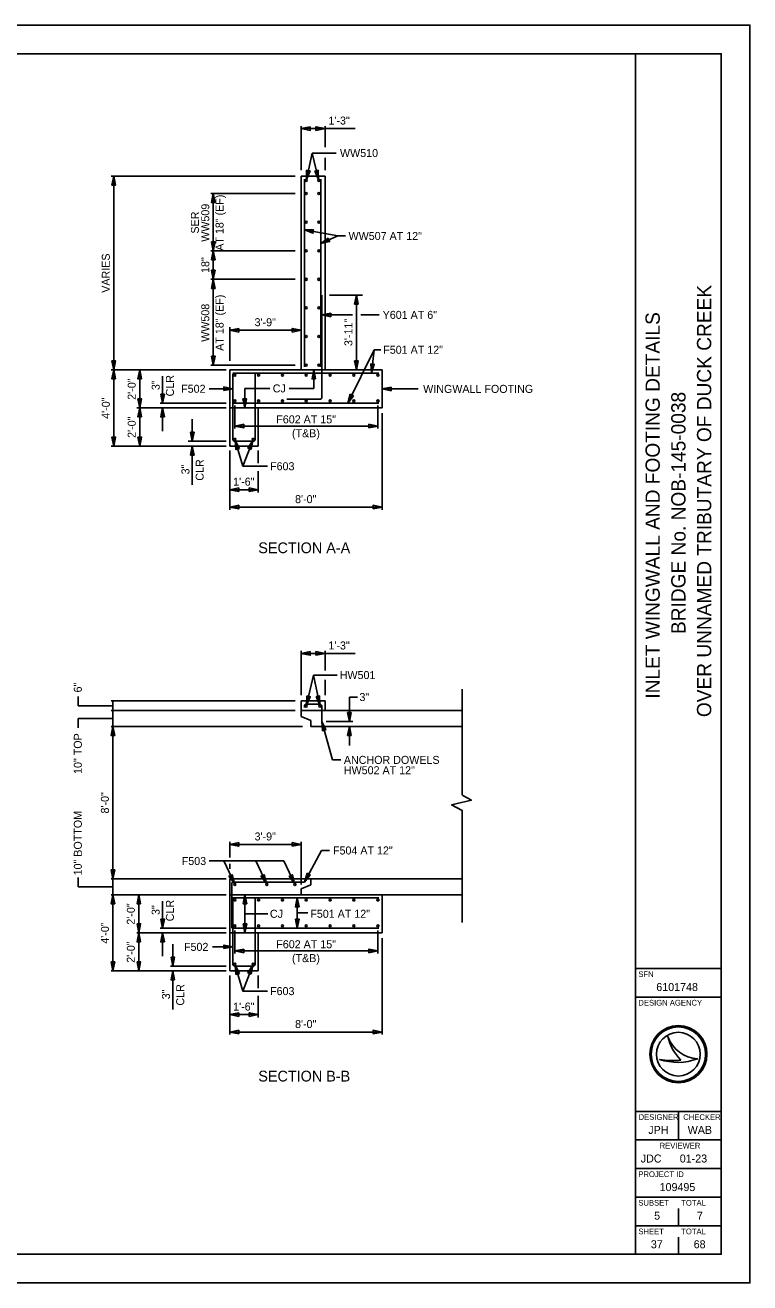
# Model space of a CAD drawing. Extents: x -375 to 456, y -77 to 177.
# Drawn here: x 64 to 102, y 0 to 66 of the extents above; entities that cross this region are included whole.
import ezdxf

# ---------------------------------------------------------------- set-up
doc = ezdxf.new("R2010")
doc.units = 0
for name, color, linetype in [('BR_P_Gen_Text', 7, 'Continuous'), ('BR_P_Slab_Reinforcing', 7, 'Continuous'), ('BR_P_Sub_Deep_Reinforcing', 7, 'Continuous'), ('DR_P_Culvert', 7, 'Continuous'), ('SH_Border', 7, 'Continuous'), ('SH_Cut_Line', 7, 'Continuous'), ('SH_Data', 7, 'Continuous'), ('TX_P_1', 7, 'Continuous')]:
    doc.layers.add(name, color=color, linetype=linetype)

msp = doc.modelspace()

# ---------------------------------------------------------------- linework, layer by layer
at = {"layer": 'BR_P_Gen_Text'}
for points in [[(78.928, 60.667), (78.928, 60.478), (78.456, 60.573)], [(79.233, 60.478), (79.233, 60.667), (79.706, 60.573)], [(78.737, 58.391), (78.922, 58.351), (78.73, 57.909)], [(79.165, 58.344), (79.349, 58.39), (79.372, 57.908)], [(68.717, 57.606), (68.528, 57.606), (68.623, 58.078)], [(73.939, 56.689), (73.75, 56.689), (73.844, 57.162)], [(79.104, 55.262), (79.071, 55.076), (78.622, 55.252)], [(79.875, 54.819), (79.95, 54.646), (79.479, 54.545)], [(73.75, 54.634), (73.939, 54.634), (73.844, 54.162)], [(73.939, 53.689), (73.75, 53.689), (73.844, 54.162)], [(73.75, 53.134), (73.939, 53.134), (73.844, 52.662)], [(73.939, 52.189), (73.75, 52.189), (73.844, 52.662)], [(81.448, 51.359), (81.259, 51.359), (81.353, 51.832)], [(80.011, 50.89), (80.011, 50.701), (79.539, 50.796)], [(75.178, 50.086), (75.178, 49.897), (74.706, 49.992)], [(77.983, 49.897), (77.983, 50.086), (78.456, 49.992)], [(68.528, 48.384), (68.717, 48.384), (68.623, 47.912)], [(73.75, 48.634), (73.939, 48.634), (73.844, 48.162)], [(81.259, 48.384), (81.448, 48.384), (81.353, 47.912)], [(82.106, 48.226), (82.293, 48.203), (82.142, 47.745)], [(68.717, 47.439), (68.528, 47.439), (68.623, 47.912)], [(70.078, 47.439), (69.889, 47.439), (69.983, 47.912)], [(79.213, 47.439), (79.024, 47.439), (79.118, 47.912)], [(74.4, 46.825), (74.4, 47.014), (74.872, 46.919)], [(83.178, 47.006), (83.178, 46.817), (82.706, 46.912)], [(69.889, 46.384), (70.078, 46.384), (69.983, 45.912)], [(71.087, 46.634), (71.276, 46.634), (71.182, 46.162)], [(75.401, 46.384), (75.59, 46.384), (75.495, 45.912)], [(81.028, 46.627), (81.198, 46.543), (80.903, 46.162)], [(70.078, 45.439), (69.889, 45.439), (69.983, 45.912)], [(71.276, 45.439), (71.087, 45.439), (71.182, 45.912)], [(75.445, 45.056), (75.445, 44.867), (74.972, 44.962)], [(82.013, 44.867), (82.013, 45.056), (82.485, 44.962)], [(68.528, 44.384), (68.717, 44.384), (68.623, 43.912)], [(69.889, 44.384), (70.078, 44.384), (69.983, 43.912)], [(72.648, 44.634), (72.837, 44.634), (72.742, 44.162)], [(72.837, 43.439), (72.648, 43.439), (72.742, 43.912)], [(75.215, 43.785), (75.034, 43.73), (74.988, 44.21)], [(75.838, 43.736), (75.662, 43.804), (75.919, 44.211)], [(75.178, 41.717), (75.178, 41.528), (74.706, 41.622)], [(75.733, 41.528), (75.733, 41.717), (76.206, 41.622)], [(75.178, 40.802), (75.178, 40.613), (74.706, 40.707)], [(82.233, 40.613), (82.233, 40.802), (82.706, 40.707)], [(78.928, 33.123), (78.928, 32.934), (78.456, 33.028)], [(79.233, 32.934), (79.233, 33.123), (79.706, 33.028)], [(78.749, 30.802), (78.933, 30.759), (78.735, 30.32)], [(79.24, 30.763), (79.425, 30.802), (79.429, 30.32)], [(80.889, 29.923), (81.078, 29.923), (80.983, 29.451)], [(68.67, 28.728), (68.481, 28.728), (68.576, 29.201)], [(79.758, 29.022), (79.576, 28.97), (79.539, 29.451)], [(81.078, 28.728), (80.889, 28.728), (80.983, 29.201)], [(75.178, 23.1), (75.178, 22.911), (74.706, 23.006)], [(77.983, 22.911), (77.983, 23.1), (78.456, 23.006)], [(68.481, 21.673), (68.67, 21.673), (68.576, 21.201)], [(74.664, 21.338), (74.836, 21.418), (74.949, 20.95)], [(76.344, 21.338), (76.515, 21.418), (76.629, 20.95)], [(77.821, 21.338), (77.993, 21.418), (78.106, 20.95)], [(78.769, 21.495), (78.935, 21.405), (78.628, 21.034)], [(68.67, 19.895), (68.481, 19.895), (68.576, 20.367)], [(70.031, 19.895), (69.842, 19.895), (69.936, 20.367)], [(75.598, 19.895), (75.409, 19.895), (75.504, 20.367)], [(78.343, 19.728), (78.154, 19.728), (78.249, 20.201)], [(69.842, 18.84), (70.031, 18.84), (69.936, 18.367)], [(71.087, 19.09), (71.276, 19.09), (71.182, 18.617)], [(75.409, 18.84), (75.598, 18.84), (75.504, 18.367)], [(78.154, 19.09), (78.343, 19.09), (78.249, 18.617)], [(70.031, 17.895), (69.842, 17.895), (69.936, 18.367)], [(71.276, 17.895), (71.087, 17.895), (71.182, 18.367)], [(74.4, 17.537), (74.4, 17.726), (74.872, 17.631)], [(75.445, 17.512), (75.445, 17.323), (74.972, 17.417)], [(82.013, 17.323), (82.013, 17.512), (82.485, 17.417)], [(68.481, 16.84), (68.67, 16.84), (68.576, 16.367)], [(69.842, 16.84), (70.031, 16.84), (69.936, 16.367)], [(71.627, 17.09), (71.816, 17.09), (71.722, 16.617)], [(75.215, 16.24), (75.034, 16.186), (74.988, 16.665)], [(75.838, 16.192), (75.662, 16.26), (75.919, 16.667)], [(71.816, 15.895), (71.627, 15.895), (71.722, 16.367)], [(75.178, 14.172), (75.178, 13.983), (74.706, 14.078)], [(75.733, 13.983), (75.733, 14.172), (76.206, 14.078)], [(75.178, 13.257), (75.178, 13.068), (74.706, 13.163)], [(82.233, 13.068), (82.233, 13.257), (82.706, 13.163)]]:
    msp.add_lwpolyline(points, close=True, dxfattribs=at)
at = {"layer": 'BR_P_Slab_Reinforcing'}
for centre in [(78.719, 57.856), (79.385, 57.856), (78.719, 57.162), (79.385, 57.162), (78.719, 55.662), (79.385, 55.662), (78.719, 54.162), (79.385, 54.162), (78.719, 52.662), (79.385, 52.662), (78.719, 51.162), (79.385, 51.162), (78.719, 49.662), (79.385, 49.662), (78.719, 48.162), (79.385, 48.162), (74.972, 47.637), (76.222, 47.637), (77.472, 47.637), (78.722, 47.637), (79.972, 47.637), (81.222, 47.637), (82.485, 47.637), (74.972, 46.276), (76.222, 46.276), (77.472, 46.276), (78.722, 46.276), (79.972, 46.276), (81.222, 46.276), (82.485, 46.276), (74.972, 44.262), (75.939, 44.262), (78.722, 30.267), (79.441, 30.267), (74.972, 20.901), (76.652, 20.901), (78.129, 20.901), (74.972, 20.093), (76.222, 20.093), (77.472, 20.093), (78.722, 20.093), (79.972, 20.093), (81.222, 20.093), (82.485, 20.093), (74.972, 18.731), (76.222, 18.731), (77.472, 18.731), (78.722, 18.731), (79.972, 18.731), (81.222, 18.731), (82.485, 18.731), (74.972, 16.717), (75.939, 16.717)]:
    msp.add_circle(centre, 0.0542, dxfattribs=at)
at = {"layer": 'BR_P_Sub_Deep_Reinforcing'}
for p, q in [((78.622, 48.078), (78.622, 57.912)), ((79.479, 48.078), (79.479, 57.912)), ((79.539, 46.465), (79.539, 51.832)), ((82.539, 47.745), (74.872, 47.745)), ((74.872, 47.707), (74.872, 44.262)), ((76.039, 44.262), (76.039, 47.707)), ((77.709, 46.365), (79.439, 46.365)), ((82.539, 46.162), (74.872, 46.162)), ((74.972, 44.162), (75.939, 44.162)), ((79.439, 30.367), (78.722, 30.367)), ((78.622, 30.267), (78.622, 30.201)), ((79.539, 29.451), (79.539, 30.267)), ((74.812, 18.617), (74.812, 20.934)), ((74.912, 21.034), (78.628, 21.034)), ((82.539, 20.201), (74.872, 20.201)), ((74.872, 20.163), (74.872, 16.717)), ((76.039, 16.717), (76.039, 20.163)), ((82.539, 18.617), (74.872, 18.617)), ((74.972, 16.617), (75.939, 16.617))]:
    msp.add_line(p, q, dxfattribs=at)
for centre, start, end in [((79.439, 46.465), 270, 0), ((74.972, 44.262), 180, 270), ((75.939, 44.262), 270, 0), ((78.722, 30.267), 90, 180), ((79.439, 30.267), 0, 90), ((74.912, 20.934), 90, 180), ((74.972, 16.717), 180, 270), ((75.939, 16.717), 270, 360)]:
    msp.add_arc(centre, 0.1, start, end, dxfattribs=at)
at = {"layer": 'DR_P_Culvert'}
for p, q in [((78.456, 47.912), (78.456, 58.078)), ((78.456, 58.078), (79.706, 58.078)), ((79.706, 47.912), (79.706, 58.078)), ((78.456, 47.912), (74.706, 47.912)), ((74.706, 47.912), (74.706, 43.912)), ((78.456, 47.912), (79.706, 47.912)), ((82.706, 47.912), (79.706, 47.912)), ((82.706, 47.912), (82.706, 45.912)), ((76.206, 45.912), (74.706, 45.912)), ((82.706, 45.912), (76.206, 45.912)), ((76.206, 45.912), (76.206, 43.912)), ((76.206, 43.912), (74.706, 43.912)), ((86.896, 31.149), (86.896, 25.656)), ((78.456, 30.034), (78.456, 30.534)), ((78.456, 30.534), (79.706, 30.534)), ((79.706, 30.034), (79.706, 30.534)), ((78.456, 30.034), (86.896, 30.034)), ((78.456, 30.034), (78.456, 29.721)), ((78.456, 29.721), (78.956, 29.513)), ((78.956, 29.513), (78.956, 29.201)), ((78.956, 29.201), (86.896, 29.201)), ((78.956, 21.201), (74.706, 21.201)), ((74.706, 20.367), (74.706, 21.201)), ((78.956, 21.201), (86.896, 21.201)), ((78.956, 20.888), (78.956, 21.201)), ((78.456, 20.68), (78.956, 20.888)), ((78.456, 20.367), (78.456, 20.68)), ((74.706, 20.367), (74.706, 16.367)), ((78.456, 20.367), (74.706, 20.367)), ((78.456, 20.367), (86.896, 20.367)), ((82.706, 20.367), (82.706, 18.367)), ((76.206, 18.367), (74.706, 18.367)), ((76.206, 16.367), (76.206, 18.367)), ((76.206, 18.367), (82.706, 18.367)), ((74.706, 16.367), (76.206, 16.367))]:
    msp.add_line(p, q, dxfattribs=at)
msp.add_lwpolyline([(86.947, 25.568), (87.386, 25.324), (86.347, 25.077), (86.896, 24.791), (86.896, 18.918)], dxfattribs=at)
msp.add_arc((86.996, 25.656), 0.1, 180, 240.89456, dxfattribs=at)
at = {"layer": 'SH_Border'}
for p, q in [((96, 1.5), (96, 64.5)), ((96, 16.5), (100.5, 16.5)), ((96, 15), (100.5, 15)), ((96, 9), (100.5, 9)), ((98.25, 9), (98.25, 7.5)), ((96, 7.5), (100.5, 7.5)), ((96, 6), (100.5, 6)), ((96, 4.5), (100.5, 4.5)), ((96, 3), (100.5, 3))]:
    msp.add_line(p, q, dxfattribs=at)
msp.add_lwpolyline([(4.5, 64.5), (100.5, 64.5), (100.5, 1.5), (4.5, 1.5)], close=True, dxfattribs=at)
at = {"layer": 'SH_Cut_Line'}
msp.add_lwpolyline([(0, 0), (102, 0), (102, 66), (0, 66)], close=True, dxfattribs=at)
at = {"layer": 'SH_Data'}
for p, q in [((97.702, 12.929), (97.702, 12.929)), ((98.25, 12), (98.25, 12)), ((97.252, 11.729), (97.251, 11.729)), ((99.262, 11.756), (99.262, 11.756)), ((98.25, 3), (98.25, 3.9)), ((97.125, 2.025), (97.125, 2.025)), ((98.25, 1.5), (98.25, 2.4))]:
    msp.add_line(p, q, dxfattribs=at)
for radius in [1.5, 1.43, 1.43, 1.147]:
    msp.add_circle((98.25, 12), radius, dxfattribs=at)
for centre, radius, start, end in [((99.348, 13.493), 1.74, 198.92567, 198.93195), ((100.04, 13.41), 2.387, 191.63793, 191.64215), ((99.348, 13.493), 1.74, 198.93195, 267.16574), ((100.04, 13.41), 2.387, 191.64215, 226.09467), ((98.218, 14.61), 3.039, 251.45274, 251.45764), ((98.218, 14.61), 3.039, 251.45764, 290.08324), ((97.944, 15.463), 3.798, 259.49639, 259.49952), ((97.944, 15.463), 3.798, 259.49952, 276.66723)]:
    msp.add_arc(centre, radius, start, end, dxfattribs=at)
at = {"layer": 'TX_P_1'}
for p, q in [((78.456, 58.393), (78.456, 60.703)), ((78.456, 60.573), (81.295, 60.573)), ((79.706, 59.599), (79.706, 60.703)), ((78.73, 57.909), (79.026, 59.29)), ((79.372, 57.908), (79.026, 59.29)), ((79.026, 59.29), (80.299, 59.29)), ((79.706, 58.393), (79.706, 59.034)), ((78.144, 58.078), (68.481, 58.078)), ((68.623, 47.912), (68.623, 58.078)), ((78.144, 57.162), (73.722, 57.162)), ((73.844, 54.162), (73.844, 57.162)), ((78.622, 55.252), (80.385, 54.936)), ((79.479, 54.545), (80.385, 54.936)), ((80.385, 54.936), (80.775, 54.936)), ((78.144, 54.162), (73.722, 54.162)), ((73.844, 52.662), (73.844, 54.162)), ((78.144, 52.662), (73.722, 52.662)), ((73.844, 48.162), (73.844, 52.662)), ((79.942, 51.832), (81.673, 51.832)), ((81.353, 51.832), (81.353, 47.912)), ((79.539, 50.796), (81.141, 50.796)), ((81.59, 50.796), (82.543, 50.796)), ((74.706, 48.376), (74.706, 50.148)), ((74.706, 49.992), (78.456, 49.992)), ((80.903, 46.162), (82.292, 48.966)), ((82.142, 47.745), (82.292, 48.966)), ((82.292, 48.966), (82.641, 48.966)), ((74.522, 47.912), (68.481, 47.912)), ((68.623, 47.912), (68.623, 43.912)), ((69.983, 47.912), (69.983, 45.912)), ((71.182, 46.162), (71.182, 47.578)), ((78.144, 48.162), (73.722, 48.162)), ((79.118, 47.912), (79.118, 46.937)), ((74.872, 46.919), (73.622, 46.919)), ((76.813, 46.937), (75.495, 46.937)), ((75.495, 45.912), (75.495, 46.937)), ((77.819, 46.937), (79.118, 46.937)), ((82.706, 46.912), (84.588, 46.912)), ((74.522, 45.912), (69.834, 45.912)), ((69.983, 45.912), (69.983, 43.912)), ((74.522, 46.162), (71.059, 46.162)), ((71.182, 44.69), (71.182, 45.912)), ((74.972, 46.038), (74.972, 44.83)), ((82.485, 46.038), (82.485, 44.83)), ((82.706, 45.632), (82.706, 40.571)), ((72.742, 45.318), (72.742, 44.162)), ((74.972, 44.962), (82.485, 44.962)), ((74.522, 43.912), (68.481, 43.912)), ((74.522, 44.162), (72.528, 44.162)), ((72.742, 43.912), (72.742, 41.882)), ((74.706, 43.671), (74.706, 40.571)), ((74.988, 44.21), (75.398, 42.853)), ((75.919, 44.211), (75.398, 42.853)), ((76.206, 43.009), (76.206, 43.671)), ((75.398, 42.853), (76.685, 42.853)), ((76.206, 42.601), (76.206, 41.469)), ((74.706, 41.622), (76.206, 41.622)), ((74.706, 40.707), (82.706, 40.707)), ((78.456, 30.848), (78.456, 33.159)), ((78.456, 33.028), (81.295, 33.028)), ((79.706, 32.13), (79.706, 33.159)), ((78.735, 30.32), (79.099, 31.895)), ((79.429, 30.32), (79.099, 31.895)), ((79.099, 31.895), (80.338, 31.895)), ((79.706, 30.848), (79.706, 31.645)), ((66.756, 30.284), (66.756, 30.77)), ((78.139, 30.534), (68.481, 30.534)), ((68.576, 30.034), (68.576, 30.534)), ((80.983, 30.741), (81.415, 30.741)), ((80.983, 29.451), (80.983, 30.741)), ((68.576, 30.284), (66.756, 30.284)), ((78.139, 30.034), (68.481, 30.034)), ((68.576, 29.201), (68.576, 30.034)), ((68.576, 29.617), (66.756, 29.617)), ((66.756, 29.131), (66.756, 29.617)), ((78.529, 29.201), (68.481, 29.201)), ((68.576, 21.201), (68.576, 29.201)), ((79.539, 29.451), (80.106, 27.443)), ((79.766, 29.451), (81.163, 29.451)), ((80.983, 28.193), (80.983, 29.201)), ((80.106, 27.443), (80.538, 27.443)), ((74.706, 22.315), (74.706, 23.141)), ((78.456, 20.901), (78.456, 23.141)), ((74.706, 23.006), (78.456, 23.006)), ((78.628, 21.034), (79.518, 22.69)), ((79.518, 22.69), (79.95, 22.69)), ((77.554, 22.138), (73.624, 22.138)), ((74.949, 20.95), (74.397, 22.138)), ((74.706, 21.721), (74.706, 21.992)), ((76.629, 20.95), (76.076, 22.138)), ((78.106, 20.95), (77.554, 22.138)), ((66.756, 20.784), (66.756, 21.27)), ((74.522, 21.201), (68.481, 21.201)), ((68.576, 20.367), (68.576, 21.201)), ((68.576, 20.784), (66.756, 20.784)), ((74.522, 20.367), (68.481, 20.367)), ((68.576, 20.367), (68.576, 16.367)), ((69.936, 20.367), (69.936, 18.367)), ((71.182, 18.617), (71.182, 20.033)), ((75.504, 18.367), (75.504, 20.367)), ((78.249, 20.201), (78.249, 18.617)), ((75.504, 19.367), (76.7, 19.367)), ((78.249, 19.409), (78.801, 19.409)), ((74.522, 18.617), (71.059, 18.617)), ((74.972, 18.494), (74.972, 17.286)), ((82.485, 18.494), (82.485, 17.286)), ((74.522, 18.367), (69.834, 18.367)), ((69.936, 18.367), (69.936, 16.367)), ((71.182, 17.145), (71.182, 18.367)), ((82.706, 18.088), (82.706, 13.026)), ((71.722, 17.774), (71.722, 16.617)), ((74.872, 17.631), (73.803, 17.631)), ((74.972, 17.417), (82.485, 17.417)), ((74.522, 16.617), (71.594, 16.617)), ((74.988, 16.665), (75.398, 15.309)), ((75.919, 16.667), (75.398, 15.309)), ((74.522, 16.367), (68.481, 16.367)), ((71.722, 16.367), (71.722, 14.338)), ((74.706, 16.126), (74.706, 13.026)), ((76.206, 15.464), (76.206, 16.126)), ((75.398, 15.309), (76.685, 15.309)), ((76.206, 15.056), (76.206, 13.925)), ((74.706, 14.078), (76.206, 14.078)), ((74.706, 13.163), (82.706, 13.163))]:
    msp.add_line(p, q, dxfattribs=at)

# ---------------------------------------------------------------- texts
at = {"layer": 'SH_Data'}
for s, p in [('OVER UNNAMED TRIBUTARY OF DUCK CREEK', (99.975, 29.688)), ('INLET WINGWALL AND FOOTING DETAILS', (97.275, 30.654)), ('BRIDGE No. NOB-145-0038', (98.625, 34.048))]:
    msp.add_text(s, height=0.75, rotation=90, dxfattribs=at).set_placement(p)
for s, height, p in [('SECTION A-A', 0.56461, (76.206, 38.29)), ('SFN', 0.3, (96.15, 16.05)), ('6101748', 0.42, (97.09, 15.315)), ('DESIGN AGENCY', 0.3, (96.15, 14.55)), ('SECTION B-B', 0.56461, (76.206, 10.566)), ('DESIGNER', 0.3, (96.162, 8.55)), ('CHECKER', 0.3, (98.506, 8.55)), ('JPH', 0.42, (96.67, 7.815)), ('WAB', 0.42, (98.738, 7.815)), ('REVIEWER', 0.3, (97.265, 7.05)), ('JDC', 0.42, (96.274, 6.315)), ('01-23', 0.42, (98.323, 6.315)), ('PROJECT ID', 0.3, (96.15, 5.55)), ('109495', 0.42, (97.264, 4.815)), ('SUBSET', 0.3, (96.15, 4.05)), ('TOTAL', 0.3, (98.4, 4.05)), ('5', 0.42, (96.977, 3.315)), ('7', 0.42, (99.223, 3.315)), ('SHEET', 0.3, (96.15, 2.55)), ('TOTAL', 0.3, (98.4, 2.55)), ('37', 0.42, (96.805, 1.815)), ('68', 0.42, (99.053, 1.815))]:
    msp.add_text(s, height=height, dxfattribs=at).set_placement(p)
at = {"layer": 'TX_P_1'}
for s, p in [('1\'-3"', (79.886, 60.783)), ('WW510', (80.492, 59.08)), ('WW507 AT 12"', (80.941, 54.726)), ('Y601 AT 6"', (82.731, 50.586)), ('3\'-9"', (76.01, 50.202)), ('F501 AT 12"', (82.762, 48.756)), ('F502', (72.157, 46.709)), ('CJ', (76.964, 46.727)), ('WINGWALL FOOTING', (84.857, 46.702)), ('F602 AT 15"', (77.149, 45.103)), ('(T&B)', (77.973, 44.375)), ('F603', (76.823, 42.643)), ('1\'-6"', (74.885, 41.832)), ('8\'-0"', (78.135, 40.917)), ('1\'-3"', (79.886, 33.238)), ('HW501', (80.478, 31.685)), ('3"', (81.512, 30.531)), ('ANCHOR DOWELS', (80.695, 27.233)), ('HW502 AT 12"', (80.695, 26.69)), ('3\'-9"', (76.01, 23.216)), ('F504 AT 12"', (80.125, 22.48)), ('F503', (72.189, 21.928)), ('CJ', (76.814, 19.157)), ('F501 AT 12"', (78.934, 19.157)), ('F502', (72.306, 17.421)), ('F602 AT 15"', (77.149, 17.559)), ('(T&B)', (77.973, 16.831)), ('F603', (76.823, 15.099)), ('1\'-6"', (74.885, 14.288)), ('8\'-0"', (78.135, 13.373))]:
    msp.add_text(s, height=0.42, dxfattribs=at).set_placement(p)
for s, p in [('AT 18" (EF)', (74.382, 54.161)), ('SER', (73.091, 55.062)), ('WW509', (73.634, 54.632)), ('VARIES', (68.413, 51.956)), ('18"', (73.634, 52.995)), ('AT 18" (EF)', (74.382, 48.911)), ('WW508', (73.634, 49.382)), ('3\'-11"', (81.143, 49.16)), ('CLR', (71.778, 46.517)), ('2\'-0"', (69.773, 46.341)), ('3"', (71.031, 46.847)), ('4\'-0"', (68.413, 45.341)), ('2\'-0"', (69.773, 44.341)), ('3"', (72.592, 42.424)), ('CLR', (73.339, 42.094)), ('6"', (66.945, 30.983)), ('10" TOP', (66.945, 26.707)), ('8\'-0"', (68.366, 24.63)), ('10" BOTTOM', (66.945, 21.382)), ('2\'-0"', (69.726, 18.797)), ('CLR', (71.778, 18.973)), ('3"', (71.031, 19.302)), ('4\'-0"', (68.366, 17.797)), ('2\'-0"', (69.726, 16.797)), ('3"', (71.571, 14.879)), ('CLR', (72.318, 14.55))]:
    msp.add_text(s, height=0.42, rotation=90, dxfattribs=at).set_placement(p)

doc.saveas('drawing.dxf')
